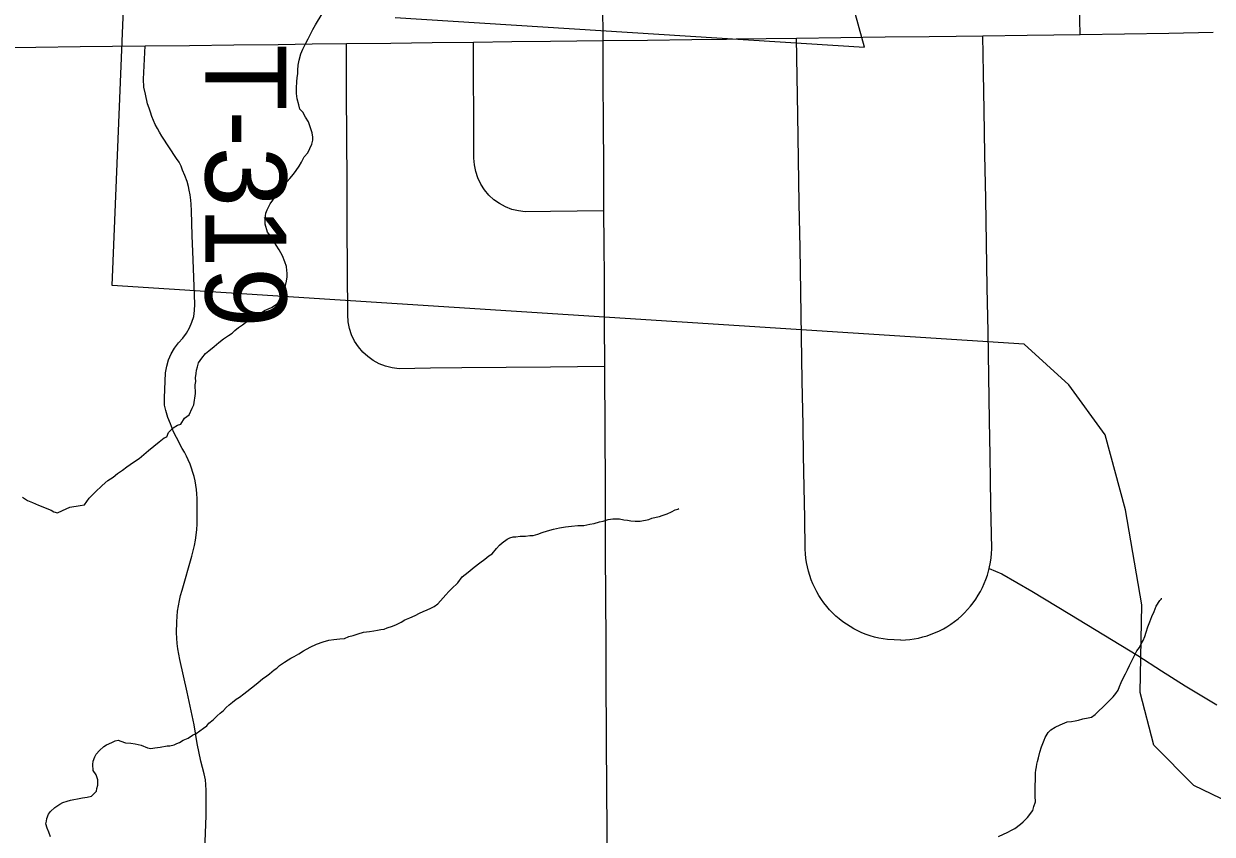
# Model space of a CAD drawing. Extents: x -11.4 to 84.1, y 11.1 to 59.
# Drawn here: x 26.89 to 27.723, y 45.388 to 45.956 of the extents above; entities that cross this region are included whole.
import ezdxf

# ---------------------------------------------------------------- set-up
doc = ezdxf.new("R2010")
doc.units = 0
for name, color, linetype in [('GM_X_Corporation', 7, 'Continuous'), ('GM_X_County_Road', 7, 'Continuous'), ('GM_X_Minor_River', 7, 'Continuous'), ('GM_X_Township_Road', 7, 'Continuous'), ('GM_X_Township_Road_Text', 7, 'Continuous')]:
    doc.layers.add(name, color=color, linetype=linetype)

msp = doc.modelspace()

# ---------------------------------------------------------------- linework, layer by layer
at = {"layer": 'GM_X_Corporation'}
for points in [[(27.15053, 45.96055), (27.47941, 45.93974), (27.43663, 46.09513)], [(27.76133, 45.39765), (27.71045, 45.42236), (27.68235, 45.45048), (27.67285, 45.48733), (27.67398, 45.54887), (27.66258, 45.61536), (27.64814, 45.66816), (27.6227, 45.70312), (27.59156, 45.73162), (26.95209, 45.77262), (26.96335, 46.04662)]]:
    msp.add_lwpolyline(points, dxfattribs=at)
at = {"layer": 'GM_X_County_Road'}
for points in [[(27.29742, 45.716), (27.29726, 45.74707), (27.2971, 45.77813), (27.29697, 45.80155), (27.29685, 45.82496), (27.29669, 45.85603), (27.29653, 45.8871), (27.29638, 45.91573), (27.29624, 45.94436), (27.29613, 45.97072)], [(27.38265, 45.94548), (27.38945, 45.94556), (27.4106, 45.94584), (27.43175, 45.94611), (27.46282, 45.94651), (27.49389, 45.94691), (27.52495, 45.94731), (27.54374, 45.94755), (27.56252, 45.94779), (27.59358, 45.9482), (27.61218, 45.94843), (27.63079, 45.94868), (27.66184, 45.94907), (27.6929, 45.94948), (27.72396, 45.95024)], [(26.8674, 45.93945), (26.89846, 45.9398), (26.92953, 45.94016), (26.95234, 45.94042), (26.97515, 45.94069), (27.00622, 45.94104), (27.03728, 45.94139), (27.06835, 45.94175), (27.0923, 45.94202), (27.11625, 45.94229)], [(27.11625, 45.94229), (27.14732, 45.94266), (27.17629, 45.94299), (27.20527, 45.94332), (27.23233, 45.94363), (27.25938, 45.94394), (27.27781, 45.94415), (27.29624, 45.94436), (27.32731, 45.94476), (27.35838, 45.94517), (27.38265, 45.94548)], [(27.29912, 45.35903), (27.29897, 45.3901), (27.29882, 45.42117), (27.29866, 45.45224), (27.29858, 45.4688), (27.2985, 45.48537), (27.29841, 45.50432), (27.29833, 45.52327), (27.29817, 45.55434), (27.29802, 45.58541), (27.29793, 45.60172), (27.29785, 45.61803), (27.29758, 45.68465), (27.2975, 45.70033), (27.29742, 45.716)]]:
    msp.add_lwpolyline(points, dxfattribs=at)
at = {"layer": 'GM_X_Minor_River'}
for points in [[(26.99479, 45.67286), (26.99779, 45.67481), (27.00006, 45.67561), (27.00265, 45.67983), (27.00603, 45.68217), (27.00823, 45.68677), (27.00933, 45.68907), (27.01034, 45.69707), (27.01023, 45.70315), (27.01058, 45.70544), (27.01053, 45.7081), (27.01086, 45.71115), (27.0112, 45.71344), (27.01192, 45.71573), (27.01264, 45.7184), (27.01486, 45.72186), (27.01747, 45.72495), (27.01971, 45.72689), (27.02346, 45.72999), (27.02683, 45.73271), (27.0302, 45.73542), (27.03358, 45.73776), (27.03622, 45.73932), (27.03808, 45.74126), (27.04071, 45.7432), (27.04333, 45.74515), (27.04633, 45.74748), (27.05047, 45.74983), (27.05461, 45.75218), (27.05874, 45.75529), (27.06364, 45.75727), (27.06627, 45.75883), (27.06815, 45.76038), (27.06961, 45.76345), (27.07147, 45.76614), (27.07257, 45.76844), (27.07364, 45.77264), (27.07435, 45.7757), (27.07468, 45.77874), (27.07463, 45.7814), (27.0746, 45.78331), (27.07417, 45.78596), (27.07298, 45.78936), (27.07139, 45.79352), (27.06904, 45.79766), (27.06708, 45.80106), (27.06553, 45.80331), (27.06398, 45.80519), (27.06279, 45.80783), (27.06086, 45.81008), (27.05924, 45.81576), (27.05919, 45.8188), (27.05952, 45.82146), (27.05987, 45.82337), (27.06059, 45.82567), (27.0617, 45.82758), (27.0628, 45.82988), (27.06466, 45.83257), (27.06799, 45.83757), (27.07133, 45.84219), (27.07469, 45.84567), (27.07656, 45.8476), (27.07917, 45.85069), (27.08102, 45.85338), (27.08325, 45.85646), (27.08472, 45.85914), (27.08656, 45.86298), (27.08917, 45.86568), (27.09064, 45.86875), (27.09211, 45.87181), (27.09282, 45.87449), (27.09278, 45.87677), (27.09235, 45.8798), (27.09076, 45.88396), (27.08957, 45.88736), (27.08761, 45.89075), (27.08565, 45.89414), (27.08372, 45.89639), (27.0829, 45.89942), (27.0817, 45.90358), (27.08125, 45.90738), (27.08119, 45.91118), (27.0815, 45.91537), (27.08183, 45.91842), (27.08216, 45.92108), (27.08212, 45.92374), (27.08244, 45.92717), (27.08314, 45.93061), (27.08421, 45.93519), (27.08567, 45.93825), (27.08751, 45.94208), (27.08935, 45.94554), (27.09119, 45.94899), (27.09266, 45.95206), (27.0945, 45.95551), (27.09931, 45.96319)], [(26.88925, 45.62435), (26.89271, 45.62213), (26.89615, 45.62066), (26.90036, 45.61883), (26.90916, 45.61517), (26.91107, 45.61406), (26.91374, 45.61335), (26.91714, 45.61492), (26.92241, 45.61729), (26.92961, 45.61855), (26.93264, 45.61898), (26.93598, 45.6236), (26.94009, 45.62785), (26.94495, 45.63249), (26.94907, 45.63598), (26.95283, 45.63833), (26.95582, 45.64104), (26.9592, 45.64337), (26.9622, 45.6457), (26.96708, 45.64883), (26.97084, 45.65155), (26.97421, 45.65427), (26.97758, 45.65699), (26.98133, 45.66009), (26.98508, 45.66319), (26.98845, 45.66591), (26.99033, 45.6667), (26.99142, 45.66976), (26.99479, 45.67286)], [(27.30314, 45.6091), (27.3058, 45.60915), (27.3077, 45.60918), (27.31075, 45.60847), (27.31341, 45.60813), (27.3157, 45.60779), (27.31874, 45.60746), (27.32216, 45.60752), (27.32822, 45.60876), (27.33048, 45.60955), (27.33351, 45.61037), (27.33578, 45.61078), (27.33767, 45.61157), (27.34107, 45.61277), (27.34408, 45.61396), (27.34672, 45.61552), (27.34861, 45.61594), (27.34936, 45.61633)], [(26.99925, 45.45238), (27.00188, 45.45395), (27.00527, 45.45552), (27.00828, 45.45748), (27.01092, 45.45866), (27.01354, 45.4606), (27.01617, 45.46255), (27.01843, 45.46411), (27.01991, 45.46603), (27.02291, 45.46836), (27.02553, 45.47107), (27.02777, 45.47301), (27.03002, 45.47494), (27.03188, 45.47688), (27.03413, 45.47881), (27.03638, 45.48075), (27.039, 45.4827), (27.04125, 45.48426), (27.04425, 45.48659), (27.05175, 45.49241), (27.05438, 45.49436), (27.05737, 45.49707), (27.06038, 45.49902), (27.06225, 45.50057), (27.06562, 45.50329), (27.0675, 45.50446), (27.06937, 45.50639), (27.07275, 45.50873), (27.07538, 45.51029), (27.07726, 45.51146), (27.07952, 45.51264), (27.08291, 45.5146), (27.08629, 45.51656), (27.09081, 45.51929), (27.09533, 45.52127), (27.09986, 45.52286), (27.10402, 45.52407), (27.10743, 45.52451), (27.1116, 45.52496), (27.11501, 45.52539), (27.11803, 45.52659), (27.12106, 45.5274), (27.12446, 45.52859), (27.12823, 45.5298), (27.1324, 45.53024), (27.13543, 45.53068), (27.13809, 45.5311), (27.14036, 45.53152), (27.14263, 45.53193), (27.1449, 45.53273), (27.14867, 45.53394), (27.15131, 45.53512), (27.15471, 45.5367), (27.15734, 45.53826), (27.16073, 45.53984), (27.1645, 45.54142), (27.16751, 45.54299), (27.17015, 45.54417), (27.17279, 45.54536), (27.17543, 45.54654), (27.17769, 45.54772), (27.18032, 45.54967), (27.18218, 45.5516), (27.18404, 45.55391), (27.18591, 45.55584), (27.18815, 45.55816), (27.19002, 45.56009), (27.1945, 45.56435), (27.19747, 45.56858), (27.2016, 45.57169), (27.20572, 45.57518), (27.20984, 45.57829), (27.21322, 45.58101), (27.21622, 45.58334), (27.21847, 45.58452), (27.22145, 45.58837), (27.22369, 45.59069), (27.22556, 45.59224), (27.22893, 45.59495), (27.23082, 45.59575), (27.23308, 45.59654), (27.23498, 45.59658), (27.23802, 45.59701), (27.24181, 45.59707), (27.24484, 45.5975), (27.24712, 45.59753), (27.25053, 45.59835), (27.25355, 45.59954), (27.25733, 45.60074), (27.26148, 45.60195), (27.26565, 45.60278), (27.26981, 45.60361), (27.27398, 45.60406), (27.27853, 45.60452), (27.28271, 45.60459), (27.28687, 45.60542), (27.2899, 45.60584), (27.29368, 45.60705), (27.29633, 45.60747), (27.29973, 45.60867), (27.30314, 45.6091)], [(27.61326, 45.46324), (27.61665, 45.46482), (27.62155, 45.4668), (27.62458, 45.46723), (27.62724, 45.46766), (27.62951, 45.46807), (27.63253, 45.46888), (27.63632, 45.46971), (27.63859, 45.47012), (27.64122, 45.47207), (27.64346, 45.47439), (27.64682, 45.47748), (27.65131, 45.48174), (27.65392, 45.48445), (27.65578, 45.48676), (27.65726, 45.48906), (27.65836, 45.49174), (27.65945, 45.49442), (27.66092, 45.49749), (27.66239, 45.50056), (27.66386, 45.50324), (27.66533, 45.50631), (27.67047, 45.51666), (27.67233, 45.51897), (27.67343, 45.52165), (27.67491, 45.52396), (27.676, 45.52664), (27.67709, 45.5297), (27.67817, 45.53352), (27.67963, 45.53696), (27.68108, 45.54079), (27.68255, 45.54424), (27.684, 45.54806), (27.68659, 45.55191), (27.68772, 45.55307), (27.68771, 45.55345)], [(27.57352, 45.38654), (27.57691, 45.38811), (27.57955, 45.3893), (27.58294, 45.39125), (27.58482, 45.39205), (27.58895, 45.39516), (27.59082, 45.39671), (27.59381, 45.3998), (27.59752, 45.4048), (27.59824, 45.40748), (27.59932, 45.41092), (27.59926, 45.41472), (27.59919, 45.41852), (27.59912, 45.4227), (27.59945, 45.42575), (27.5994, 45.42917), (27.59936, 45.43107), (27.59971, 45.43298), (27.60005, 45.43527), (27.6004, 45.43717), (27.60075, 45.43908), (27.60146, 45.44175), (27.60254, 45.44557), (27.60361, 45.44939), (27.60543, 45.45399), (27.60616, 45.4559), (27.60838, 45.45936), (27.61025, 45.46129), (27.61326, 45.46324)], [(26.90882, 45.38625), (26.90762, 45.38965), (26.90644, 45.3923), (26.90563, 45.39533), (26.90598, 45.39723), (26.90633, 45.39914), (26.90741, 45.4022), (26.9089, 45.40413), (26.91189, 45.40684), (26.91527, 45.40917), (26.91753, 45.41035), (26.92056, 45.41116), (26.92282, 45.41196), (26.92509, 45.41238), (26.92775, 45.4128), (26.93115, 45.41362), (26.93456, 45.41405), (26.93759, 45.41486), (26.94095, 45.41834), (26.9413, 45.42025), (26.94202, 45.42254), (26.94198, 45.42444), (26.94195, 45.42634), (26.94076, 45.42975), (26.93881, 45.43276), (26.93836, 45.43693), (26.9387, 45.43922), (26.93979, 45.44228), (26.94089, 45.4442), (26.94313, 45.4469), (26.94612, 45.44961), (26.948, 45.45078), (26.95177, 45.45236), (26.95403, 45.45354), (26.9563, 45.45396), (26.95821, 45.45323), (26.96127, 45.45214), (26.96507, 45.45182), (26.96812, 45.45149), (26.97232, 45.45042), (26.9769, 45.44859), (26.97919, 45.44825), (26.98184, 45.44867), (26.98563, 45.44912), (26.99056, 45.44996), (26.99245, 45.44999), (26.99548, 45.4508), (26.99736, 45.45159), (26.99925, 45.45238)]]:
    msp.add_lwpolyline(points, dxfattribs=at)
at = {"layer": 'GM_X_Township_Road'}
for points in [[(27.63079, 45.94868), (27.63005, 45.97974)], [(27.50504, 45.52412), (27.50817, 45.52427), (27.51125, 45.52458), (27.51433, 45.52503), (27.51736, 45.52562), (27.52039, 45.52636), (27.52338, 45.52724), (27.52632, 45.52826), (27.52921, 45.52943), (27.53205, 45.53072), (27.5348, 45.53216), (27.53726, 45.53358), (27.54011, 45.5354), (27.54262, 45.53721), (27.54509, 45.53914), (27.54745, 45.54119), (27.54968, 45.54333), (27.55182, 45.54559), (27.55385, 45.54795), (27.5558, 45.5504), (27.55755, 45.55294), (27.55926, 45.55557), (27.56083, 45.55825), (27.56225, 45.56102), (27.56353, 45.56386), (27.56467, 45.56676), (27.56566, 45.56969), (27.56699, 45.57441), (27.56785, 45.57876), (27.56827, 45.58184), (27.56856, 45.58494), (27.5687, 45.58805), (27.5682, 45.61911), (27.56792, 45.63629), (27.56764, 45.65346), (27.56723, 45.67809), (27.56668, 45.70916), (27.56614, 45.74022), (27.5656, 45.77128), (27.56506, 45.80234), (27.56452, 45.83341), (27.56398, 45.86447), (27.56343, 45.89553), (27.56297, 45.92166), (27.56252, 45.94779)], [(27.01692, 45.37675), (27.01782, 45.40131), (27.01794, 45.41875), (27.01774, 45.42296), (27.01746, 45.42623), (27.01655, 45.43051), (27.01427, 45.43925), (27.01173, 45.4517), (27.00961, 45.46482), (27.00453, 45.48773), (26.99945, 45.51064), (26.99875, 45.51433), (26.99813, 45.51805), (26.99766, 45.52179), (26.99737, 45.52556), (26.99719, 45.52933), (26.99729, 45.53688), (26.99752, 45.54064), (26.99795, 45.54439), (26.99847, 45.54813), (26.99919, 45.55183), (27, 45.55552), (27.00099, 45.55916), (27.00787, 45.5831), (27.00887, 45.58673), (27.00968, 45.59041), (27.01039, 45.59412), (27.01091, 45.59783), (27.01134, 45.60158), (27.01158, 45.60534), (27.01172, 45.6091), (27.01154, 45.62351), (27.0114, 45.6266), (27.01111, 45.62966), (27.01069, 45.63272), (27.01012, 45.63575), (27.00946, 45.63876), (27.00861, 45.64173), (27.00766, 45.64467), (27.00662, 45.64756), (27.00539, 45.65041), (27.00407, 45.65319), (27.00264, 45.65591), (27.00108, 45.65858), (26.99707, 45.66618), (26.99502, 45.67004), (26.99297, 45.67574), (26.99107, 45.68028), (26.98961, 45.6851), (26.98873, 45.68889), (26.98864, 45.69391), (26.98945, 45.71146), (26.99026, 45.71607), (26.99154, 45.72055), (26.99339, 45.72484), (26.99576, 45.72888), (26.9986, 45.7326), (27.00159, 45.7359), (27.0042, 45.73931), (27.00633, 45.74301), (27.00799, 45.74694), (27.00918, 45.75105), (27.00984, 45.75526), (27.00999, 45.75954), (27.00886, 45.79059), (27.00823, 45.80784), (27.00761, 45.8251), (27.00744, 45.82962), (27.00715, 45.83255), (27.00671, 45.8362), (27.00598, 45.83956), (27.00554, 45.84219), (27.00452, 45.84555), (27.00291, 45.84979), (27.00145, 45.85359), (27.00041, 45.85638), (26.9989, 45.85906), (26.99724, 45.86167), (26.98682, 45.87749), (26.98521, 45.8801), (26.9837, 45.88279), (26.98228, 45.88553), (26.98105, 45.88834), (26.97991, 45.89119), (26.97892, 45.89411), (26.97807, 45.89707), (26.9769, 45.90006), (26.97544, 45.90678), (26.97427, 45.91175), (26.97398, 45.91745), (26.97441, 45.92666), (26.97515, 45.94069)], [(27.29742, 45.716), (27.27835, 45.71578), (27.25928, 45.71556), (27.22821, 45.71522), (27.19714, 45.71489), (27.17515, 45.71466), (27.15315, 45.71442), (27.14841, 45.71497), (27.14377, 45.7161), (27.13931, 45.71782), (27.1351, 45.72009), (27.13122, 45.72286), (27.12771, 45.7261), (27.12463, 45.72976), (27.12203, 45.73378), (27.11994, 45.73809), (27.11848, 45.74262), (27.11753, 45.7473), (27.1172, 45.75207), (27.11705, 45.78314), (27.11689, 45.81421), (27.11674, 45.84528), (27.11658, 45.87635), (27.11643, 45.90742), (27.11633, 45.92485), (27.11625, 45.94229)], [(27.29685, 45.82496), (27.27809, 45.82475), (27.25932, 45.82454), (27.24165, 45.82441), (27.23692, 45.82496), (27.23228, 45.82609), (27.22782, 45.82781), (27.2236, 45.83008), (27.21972, 45.83285), (27.21621, 45.8361), (27.21314, 45.83974), (27.21053, 45.84376), (27.20845, 45.84808), (27.20694, 45.85261), (27.20604, 45.8573), (27.20571, 45.86206), (27.20554, 45.89313), (27.20541, 45.91822), (27.20527, 45.94332)], [(27.50504, 45.52412), (27.49571, 45.52454), (27.49263, 45.52498), (27.4896, 45.52556), (27.48657, 45.52629), (27.48358, 45.52716), (27.48064, 45.52817), (27.47775, 45.52932), (27.47491, 45.53061), (27.47212, 45.53204), (27.46942, 45.53359), (27.46681, 45.53525), (27.46425, 45.53706), (27.46184, 45.53898), (27.45947, 45.54101), (27.4572, 45.54315), (27.45507, 45.5454), (27.45303, 45.54775), (27.45109, 45.55019), (27.44929, 45.55273), (27.44759, 45.55534), (27.44602, 45.55803), (27.4446, 45.56079), (27.44328, 45.56363), (27.44214, 45.5665), (27.4411, 45.56944), (27.44025, 45.57242), (27.43949, 45.57546), (27.43888, 45.5785), (27.43845, 45.58158), (27.43812, 45.58468), (27.43798, 45.58779), (27.43761, 45.60963), (27.43724, 45.63147), (27.43682, 45.65352), (27.43646, 45.67486), (27.43592, 45.70593), (27.43538, 45.73699), (27.43484, 45.76805), (27.4343, 45.79911), (27.43376, 45.83017), (27.43321, 45.86124), (27.43268, 45.8923), (27.43221, 45.9192), (27.43175, 45.94611)], [(27.56699, 45.57441), (27.57586, 45.57057), (27.59681, 45.55836), (27.62337, 45.54223), (27.64722, 45.52775), (27.67108, 45.51327), (27.68767, 45.50266), (27.70426, 45.49205), (27.72657, 45.47881)]]:
    msp.add_lwpolyline(points, dxfattribs=at)

# ---------------------------------------------------------------- texts
at = {"layer": 'GM_X_Township_Road_Text'}
msp.add_text('T-319', height=0.056818, rotation=270, dxfattribs=at).set_placement((27.01742, 45.94172))

doc.saveas('drawing.dxf')
